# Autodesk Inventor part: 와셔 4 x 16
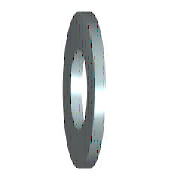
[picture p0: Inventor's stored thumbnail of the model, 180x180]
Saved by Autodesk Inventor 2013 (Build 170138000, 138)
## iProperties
IsCustomPart: 1
Created: 2012-02
Part Number: 와셔 4 x 16
Material: 강철, 연강
Description: 미터법 평면 와셔
Document SubType Name: Modeling
Standard: ANSI B18.22M
Designer: mduedu
Standard Revision: 1999
Standards Organization: ANSI
Language: ko-KR
Size Designation: 4 W
Categories: <MemberInstance><Categories><Category DisplayName="조임쇠" InternalName="e4da775c-781d-43d5-af7c-5136215cf5a6" Mnemonic="FSTN"><Category DisplayName="와셔" InternalN
Density: 1 g/cm^3
Author: mduedu
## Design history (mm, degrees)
sketch "스케치"
  geometry: C1 r 8 at (0, 0); C2 r 2.35 at (0, 0); 1 further point
  constraints: 2 centre point, 2 coincident
  dimensions: "d0" = 4.7 diameter of C2 (= SD1); "d1" = 16 diameter of C1 (= SD2)
extrude "본체" new body sketch "스케치" distance "d2" = 2.3 (= SD); taper "d3" = 0 deg
workaxis "Work Axis1"
workplane "Work Plane1"
body "Solid1"
other parameters: "SD1" = 4.7 [user parameter; used in 1 equation term], "SD2" = 16 [user parameter; used in 1 equation term], "SD" = 2.3 [user parameter; used in 1 equation term], "d4" = 0, "d5" = 0, "d6" = 0, "d7" = 0, "NND" = 4 [user parameter]
